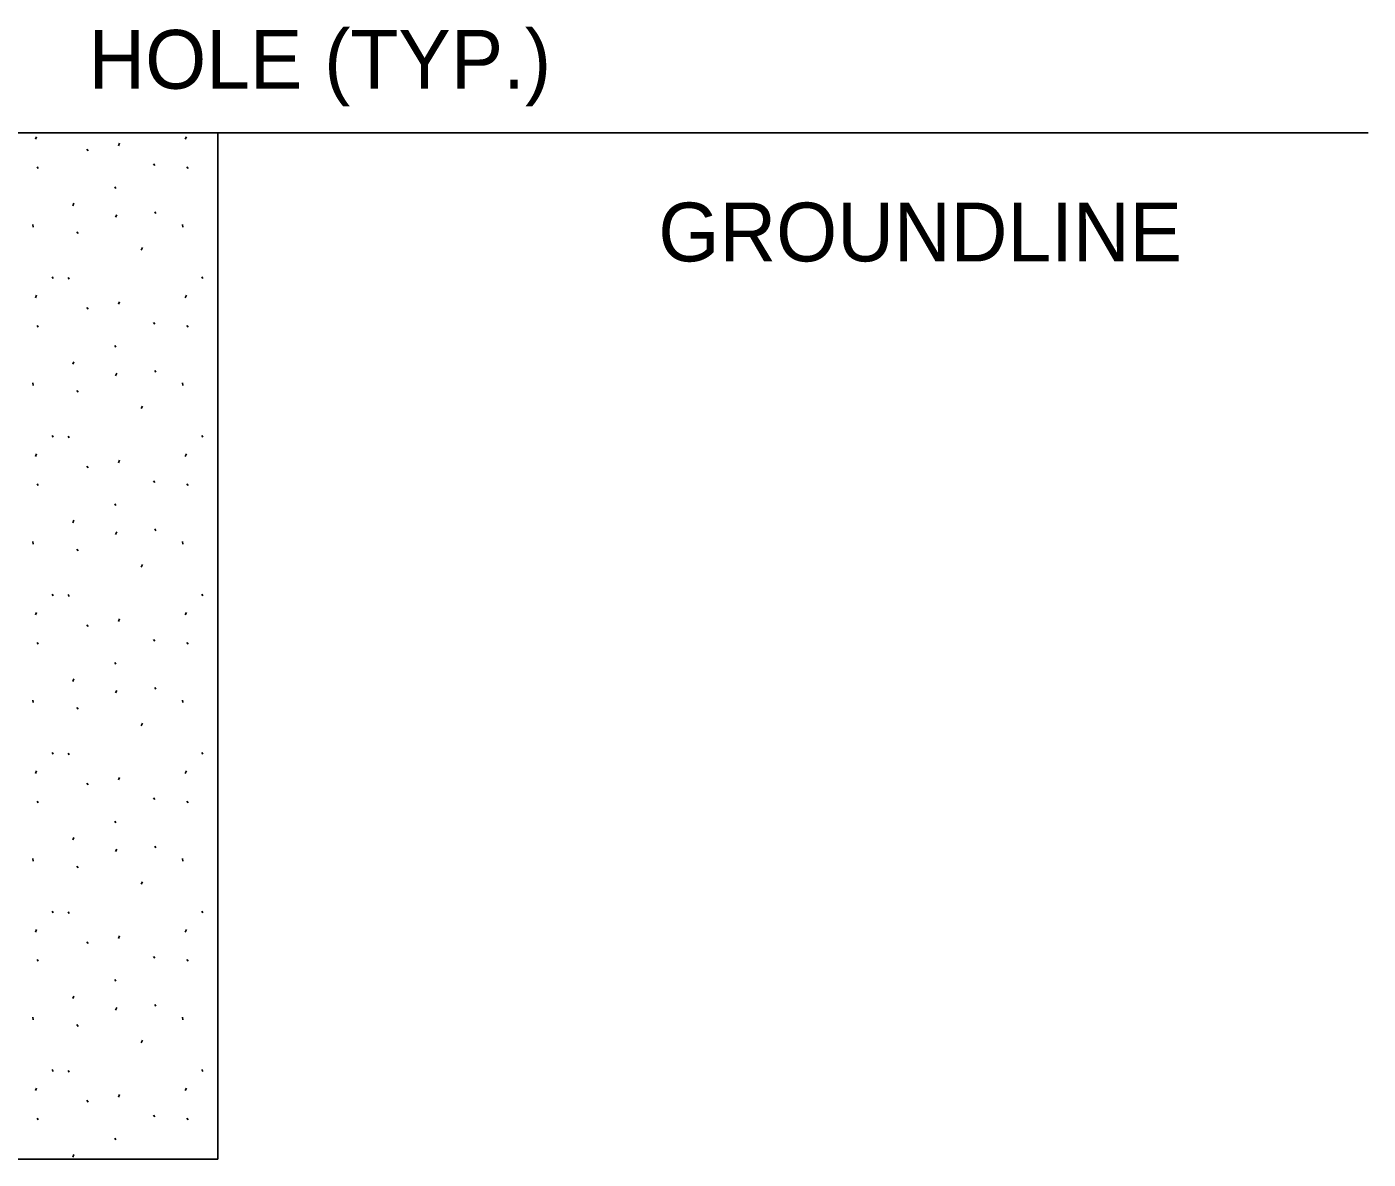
# Model space of a CAD drawing. Extents: x -2137320.7 to -2137313.2, y -2137946.3 to -2137936.1.
# Drawn here: x -2137318.564 to -2137317.194, y -2137943.591 to -2137942.435 of the extents above; entities that cross this region are included whole.
import ezdxf

# ---------------------------------------------------------------- set-up
doc = ezdxf.new("R2010")
doc.units = 0
for name, color, linetype in [('DETL-LINE', 7, 'Continuous'), ('DETL-NOTE', 7, 'Continuous'), ('DETL-PATT', 7, 'Continuous')]:
    doc.layers.add(name, color=color, linetype=linetype)

msp = doc.modelspace()

# ---------------------------------------------------------------- linework, layer by layer
at = {"layer": 'DETL-LINE'}
for p, q in [((-2137317.194, -2137942.543), (-2137318.668, -2137942.543)), ((-2137318.369, -2137943.591), (-2137318.369, -2137942.543)), ((-2137318.67, -2137943.591), (-2137318.369, -2137943.591))]:
    msp.add_line(p, q, dxfattribs=at)
at = {"layer": 'DETL-PATT'}
for p, q in [((-2137318.5552, -2137942.5496), (-2137318.554, -2137942.547)), ((-2137318.4703, -2137942.5563), (-2137318.4692, -2137942.5537)), ((-2137318.4021, -2137942.5496), (-2137318.401, -2137942.547)), ((-2137318.5025, -2137942.5596), (-2137318.5014, -2137942.5613)), ((-2137318.5534, -2137942.5778), (-2137318.5523, -2137942.5795)), ((-2137318.4344, -2137942.5747), (-2137318.4332, -2137942.5764)), ((-2137318.4004, -2137942.5778), (-2137318.3992, -2137942.5795)), ((-2137318.4741, -2137942.5982), (-2137318.473, -2137942.5999)), ((-2137318.5169, -2137942.6175), (-2137318.5158, -2137942.615)), ((-2137318.4333, -2137942.6238), (-2137318.4321, -2137942.6255)), ((-2137318.5578, -2137942.6366), (-2137318.5576, -2137942.6392)), ((-2137318.4732, -2137942.6293), (-2137318.472, -2137942.6267)), ((-2137318.4048, -2137942.6366), (-2137318.4045, -2137942.6392)), ((-2137318.5127, -2137942.6442), (-2137318.5116, -2137942.6459)), ((-2137318.447, -2137942.6627), (-2137318.4459, -2137942.6601)), ((-2137318.5382, -2137942.6902), (-2137318.5371, -2137942.6919)), ((-2137318.5218, -2137942.6909), (-2137318.5207, -2137942.6926)), ((-2137318.3852, -2137942.6902), (-2137318.384, -2137942.6919)), ((-2137318.5552, -2137942.7115), (-2137318.554, -2137942.7089)), ((-2137318.4703, -2137942.7181), (-2137318.4692, -2137942.7156)), ((-2137318.4021, -2137942.7115), (-2137318.401, -2137942.7089)), ((-2137318.5025, -2137942.7215), (-2137318.5014, -2137942.7232)), ((-2137318.5534, -2137942.7397), (-2137318.5523, -2137942.7414)), ((-2137318.4344, -2137942.7366), (-2137318.4332, -2137942.7383)), ((-2137318.4004, -2137942.7397), (-2137318.3992, -2137942.7414)), ((-2137318.4741, -2137942.7601), (-2137318.473, -2137942.7618)), ((-2137318.5169, -2137942.7794), (-2137318.5158, -2137942.7768)), ((-2137318.4732, -2137942.7912), (-2137318.472, -2137942.7886)), ((-2137318.4333, -2137942.7856), (-2137318.4321, -2137942.7874)), ((-2137318.5578, -2137942.7984), (-2137318.5576, -2137942.801)), ((-2137318.4048, -2137942.7984), (-2137318.4045, -2137942.801)), ((-2137318.5127, -2137942.8061), (-2137318.5116, -2137942.8078)), ((-2137318.447, -2137942.8246), (-2137318.4459, -2137942.822)), ((-2137318.5382, -2137942.8521), (-2137318.5371, -2137942.8538)), ((-2137318.5218, -2137942.8527), (-2137318.5207, -2137942.8545)), ((-2137318.3852, -2137942.8521), (-2137318.384, -2137942.8538)), ((-2137318.5552, -2137942.8734), (-2137318.554, -2137942.8708)), ((-2137318.4021, -2137942.8734), (-2137318.401, -2137942.8708)), ((-2137318.5025, -2137942.8834), (-2137318.5014, -2137942.8851)), ((-2137318.4703, -2137942.88), (-2137318.4692, -2137942.8774)), ((-2137318.4344, -2137942.8984), (-2137318.4332, -2137942.9002)), ((-2137318.5534, -2137942.9016), (-2137318.5523, -2137942.9033)), ((-2137318.4004, -2137942.9016), (-2137318.3992, -2137942.9033)), ((-2137318.4741, -2137942.922), (-2137318.473, -2137942.9237)), ((-2137318.5169, -2137942.9413), (-2137318.5158, -2137942.9387)), ((-2137318.4732, -2137942.9531), (-2137318.472, -2137942.9505)), ((-2137318.4333, -2137942.9475), (-2137318.4321, -2137942.9493)), ((-2137318.5578, -2137942.9603), (-2137318.5576, -2137942.9629)), ((-2137318.4048, -2137942.9603), (-2137318.4045, -2137942.9629)), ((-2137318.5127, -2137942.968), (-2137318.5116, -2137942.9697)), ((-2137318.447, -2137942.9865), (-2137318.4459, -2137942.9839)), ((-2137318.5382, -2137943.014), (-2137318.5371, -2137943.0157)), ((-2137318.5218, -2137943.0146), (-2137318.5207, -2137943.0164)), ((-2137318.3852, -2137943.014), (-2137318.384, -2137943.0157)), ((-2137318.5552, -2137943.0353), (-2137318.554, -2137943.0327)), ((-2137318.4021, -2137943.0353), (-2137318.401, -2137943.0327)), ((-2137318.5025, -2137943.0453), (-2137318.5014, -2137943.047)), ((-2137318.4703, -2137943.0419), (-2137318.4692, -2137943.0393)), ((-2137318.4344, -2137943.0603), (-2137318.4332, -2137943.0621)), ((-2137318.5534, -2137943.0634), (-2137318.5523, -2137943.0652)), ((-2137318.4004, -2137943.0634), (-2137318.3992, -2137943.0652)), ((-2137318.4741, -2137943.0839), (-2137318.473, -2137943.0856)), ((-2137318.5169, -2137943.1032), (-2137318.5158, -2137943.1006)), ((-2137318.4732, -2137943.115), (-2137318.472, -2137943.1124)), ((-2137318.4333, -2137943.1094), (-2137318.4321, -2137943.1111)), ((-2137318.5578, -2137943.1222), (-2137318.5576, -2137943.1248)), ((-2137318.5127, -2137943.1299), (-2137318.5116, -2137943.1316)), ((-2137318.4048, -2137943.1222), (-2137318.4045, -2137943.1248)), ((-2137318.447, -2137943.1484), (-2137318.4459, -2137943.1458)), ((-2137318.5382, -2137943.1759), (-2137318.5371, -2137943.1776)), ((-2137318.5218, -2137943.1765), (-2137318.5207, -2137943.1782)), ((-2137318.3852, -2137943.1759), (-2137318.384, -2137943.1776)), ((-2137318.5552, -2137943.1972), (-2137318.554, -2137943.1946)), ((-2137318.4021, -2137943.1972), (-2137318.401, -2137943.1946)), ((-2137318.5025, -2137943.2072), (-2137318.5014, -2137943.2089)), ((-2137318.4703, -2137943.2038), (-2137318.4692, -2137943.2012)), ((-2137318.5534, -2137943.2253), (-2137318.5523, -2137943.2271)), ((-2137318.4344, -2137943.2222), (-2137318.4332, -2137943.2239)), ((-2137318.4004, -2137943.2253), (-2137318.3992, -2137943.2271)), ((-2137318.4741, -2137943.2458), (-2137318.473, -2137943.2475)), ((-2137318.5169, -2137943.2651), (-2137318.5158, -2137943.2625)), ((-2137318.4732, -2137943.2769), (-2137318.472, -2137943.2743)), ((-2137318.4333, -2137943.2713), (-2137318.4321, -2137943.273)), ((-2137318.5578, -2137943.2841), (-2137318.5576, -2137943.2867)), ((-2137318.5127, -2137943.2917), (-2137318.5116, -2137943.2935)), ((-2137318.4048, -2137943.2841), (-2137318.4045, -2137943.2867)), ((-2137318.447, -2137943.3103), (-2137318.4459, -2137943.3077)), ((-2137318.5382, -2137943.3377), (-2137318.5371, -2137943.3395)), ((-2137318.5218, -2137943.3384), (-2137318.5207, -2137943.3401)), ((-2137318.3852, -2137943.3377), (-2137318.384, -2137943.3395)), ((-2137318.5552, -2137943.3591), (-2137318.554, -2137943.3565)), ((-2137318.4703, -2137943.3657), (-2137318.4692, -2137943.3631)), ((-2137318.4021, -2137943.3591), (-2137318.401, -2137943.3565)), ((-2137318.5025, -2137943.369), (-2137318.5014, -2137943.3708)), ((-2137318.5534, -2137943.3872), (-2137318.5523, -2137943.3889)), ((-2137318.4344, -2137943.3841), (-2137318.4332, -2137943.3858)), ((-2137318.4004, -2137943.3872), (-2137318.3992, -2137943.3889)), ((-2137318.4741, -2137943.4076), (-2137318.473, -2137943.4094)), ((-2137318.5169, -2137943.427), (-2137318.5158, -2137943.4244)), ((-2137318.5578, -2137943.446), (-2137318.5576, -2137943.4486)), ((-2137318.4732, -2137943.4388), (-2137318.472, -2137943.4362)), ((-2137318.4333, -2137943.4332), (-2137318.4321, -2137943.4349)), ((-2137318.4048, -2137943.446), (-2137318.4045, -2137943.4486)), ((-2137318.5127, -2137943.4536), (-2137318.5116, -2137943.4554)), ((-2137318.447, -2137943.4721), (-2137318.4459, -2137943.4696)), ((-2137318.5382, -2137943.4996), (-2137318.5371, -2137943.5014)), ((-2137318.5218, -2137943.5003), (-2137318.5207, -2137943.502)), ((-2137318.3852, -2137943.4996), (-2137318.384, -2137943.5014)), ((-2137318.5552, -2137943.521), (-2137318.554, -2137943.5184)), ((-2137318.4703, -2137943.5276), (-2137318.4692, -2137943.525)), ((-2137318.4021, -2137943.521), (-2137318.401, -2137943.5184)), ((-2137318.5025, -2137943.5309), (-2137318.5014, -2137943.5327)), ((-2137318.5534, -2137943.5491), (-2137318.5523, -2137943.5508)), ((-2137318.4344, -2137943.546), (-2137318.4332, -2137943.5477)), ((-2137318.4004, -2137943.5491), (-2137318.3992, -2137943.5508)), ((-2137318.4741, -2137943.5695), (-2137318.473, -2137943.5713)), ((-2137318.5169, -2137943.5889), (-2137318.5158, -2137943.5863))]:
    msp.add_line(p, q, dxfattribs=at)

# ---------------------------------------------------------------- texts
at = {"layer": 'DETL-NOTE'}
for s, p in [('HOLE (TYP.)', (-2137318.501, -2137942.498)), ('GROUNDLINE', (-2137317.919, -2137942.6743))]:
    msp.add_text(s, height=0.06, dxfattribs=at).set_placement(p)

doc.saveas('drawing.dxf')
